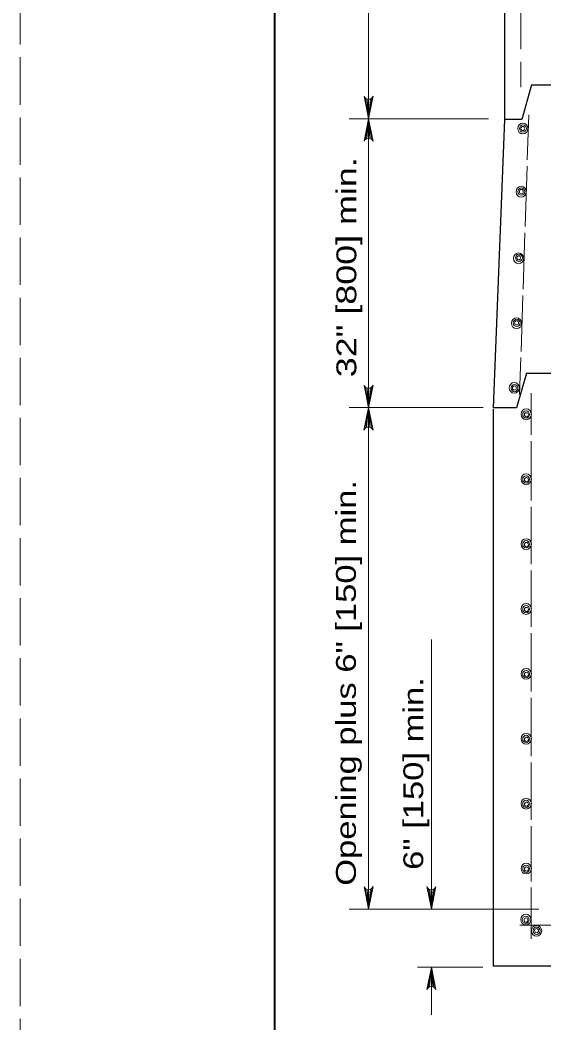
# Model space of a CAD drawing. Extents: x 808.4 to 842.4, y 1034.6 to 1056.6.
# Drawn here: x 808.44 to 812.55, y 1039.13 to 1047.01 of the extents above; entities that cross this region are included whole.
import ezdxf

# ---------------------------------------------------------------- set-up
doc = ezdxf.new("R2010")
doc.units = 0
doc.header["$LTSCALE"] = 0.062
doc.linetypes.add('LONG_DASHED', pattern=[7.5, 6, -1.5])
doc.layers.add('1', color=7, linetype='Continuous', lineweight=13)
doc.layers.add('10', color=7, linetype='Continuous')

msp = doc.modelspace()

# ---------------------------------------------------------------- linework, layer by layer
at = {"layer": '1', "linetype": 'LONG_DASHED'}
msp.add_line((812.37008, 1051.40067), (812.37008, 1046.4815), dxfattribs=at)
at = {"layer": '1'}
for p, q in [((811.17467, 1051.31167), (811.17467, 1046.23342)), ((811.15225, 1046.39358), (811.17467, 1046.23342)), ((811.16333, 1046.38817), (811.17467, 1046.23342)), ((811.19942, 1046.3955), (811.17467, 1046.23342)), ((811.18908, 1046.38933), (811.17467, 1046.23342)), ((811.17467, 1046.3865), (811.17467, 1046.23342)), ((811.022, 1046.23342), (812.11558, 1046.23342)), ((811.14983, 1046.07125), (811.17467, 1046.23342)), ((811.16025, 1046.07742), (811.17467, 1046.23342)), ((811.17467, 1046.23342), (811.17467, 1043.96608)), ((811.17467, 1046.08025), (811.17467, 1046.23342)), ((811.186, 1046.07858), (811.17467, 1046.23342)), ((811.19708, 1046.07317), (811.17467, 1046.23342)), ((812.43325, 1046.26425), (812.4215, 1045.91)), ((812.41983, 1045.86083), (812.40425, 1045.3855)), ((812.40267, 1045.33642), (812.38808, 1044.89383)), ((812.38642, 1044.84467), (812.372, 1044.40625)), ((812.3705, 1044.35717), (812.36092, 1044.06775)), ((811.15225, 1044.12375), (811.17467, 1043.9635)), ((811.16333, 1044.11825), (811.17467, 1043.9635)), ((811.19942, 1044.12558), (811.17467, 1043.9635)), ((811.18908, 1044.1195), (811.17467, 1043.9635)), ((811.17467, 1044.11667), (811.17467, 1043.9635)), ((812.45225, 1044.07833), (812.45225, 1043.75075)), ((811.022, 1043.96433), (812.07508, 1043.96433)), ((811.14967, 1043.80267), (811.17442, 1043.96475)), ((811.16, 1043.80875), (811.17442, 1043.96475)), ((811.17442, 1043.81158), (811.17442, 1043.96475)), ((811.18575, 1043.80992), (811.17442, 1043.96475)), ((811.19683, 1043.8045), (811.17442, 1043.96475)), ((811.17467, 1043.95367), (811.17467, 1040.02467)), ((812.45225, 1043.70158), (812.45225, 1043.23442)), ((812.45225, 1043.18533), (812.45225, 1042.73458)), ((812.45225, 1042.68542), (812.45225, 1042.24283)), ((811.66783, 1042.14333), (811.66783, 1040.02467)), ((812.45225, 1042.19367), (812.45225, 1041.73483)), ((812.45225, 1041.68567), (812.45225, 1041.22675)), ((812.45225, 1041.17758), (812.45225, 1040.72692)), ((812.45225, 1040.67775), (812.45225, 1040.24342)), ((811.15225, 1040.18492), (811.17467, 1040.02467)), ((811.16333, 1040.1795), (811.17467, 1040.02467)), ((811.19942, 1040.18683), (811.17467, 1040.02467)), ((811.18908, 1040.18067), (811.17467, 1040.02467)), ((811.17467, 1040.17783), (811.17467, 1040.02467)), ((811.64542, 1040.18492), (811.66783, 1040.02467)), ((811.6565, 1040.1795), (811.66783, 1040.02467)), ((811.69258, 1040.18683), (811.66783, 1040.02467)), ((811.68225, 1040.18067), (811.66783, 1040.02467)), ((811.66783, 1040.17783), (811.66783, 1040.02467)), ((812.45225, 1040.19425), (812.45225, 1039.79125)), ((812.51283, 1040.02467), (811.022, 1040.02467)), ((812.67817, 1039.89975), (812.36392, 1039.89975)), ((812.07308, 1039.56975), (811.56033, 1039.56975)), ((811.643, 1039.40758), (811.66783, 1039.56975)), ((811.65342, 1039.41375), (811.66783, 1039.56975)), ((811.66783, 1039.56975), (811.66783, 1039.19467)), ((811.66783, 1039.41658), (811.66783, 1039.56975)), ((811.67917, 1039.41492), (811.66783, 1039.56975)), ((811.69025, 1039.4095), (811.66783, 1039.56975))]:
    msp.add_line(p, q, dxfattribs=at)
at = {"layer": '1', "lineweight": 25}
for p, q in [((812.24142, 1051.31108), (812.24142, 1046.22592)), ((812.45517, 1046.49917), (816.43017, 1046.49917)), ((812.24142, 1046.22592), (812.15292, 1043.96275)), ((812.37825, 1046.22592), (812.24208, 1046.22592)), ((812.15217, 1043.95175), (812.15217, 1039.57592)), ((812.33733, 1043.96275), (812.15825, 1043.96275)), ((817.311, 1039.57592), (812.15217, 1039.57592))]:
    msp.add_line(p, q, dxfattribs=at)
at = {"layer": '1', "linetype": 'LONG_DASHED'}
msp.add_lwpolyline([(808.43883, 1034.62767), (842.43883, 1034.62767), (842.43883, 1056.62767), (808.43883, 1056.62767)], close=True, dxfattribs=at)
at = {"layer": '1', "lineweight": 25}
msp.add_lwpolyline([(810.43883, 1056.12767), (841.93883, 1056.12767), (841.93883, 1035.12767), (810.43883, 1035.12767)], close=True, dxfattribs=at)
at = {"layer": '1', "lineweight": 40}
msp.add_lwpolyline([(810.43883, 1056.12767), (841.93883, 1056.12767), (841.93883, 1035.12767), (810.43883, 1035.12767)], close=True, dxfattribs=at)
at = {"layer": '1', "lineweight": 25}
for points in [[(812.45517, 1046.49917), (812.37758, 1046.22592), (812.24408, 1046.22592)], [(812.41425, 1044.23608), (812.33658, 1043.96275), (812.15292, 1043.96275)], [(812.41425, 1044.23608), (817.05442, 1044.23608), (817.13217, 1043.96275), (817.31108, 1043.96275)]]:
    msp.add_lwpolyline(points, dxfattribs=at)
at = {"layer": '1'}
for points in [[(811.21008, 1046.41042), (811.17467, 1046.23342), (811.13925, 1046.41042)], [(811.13925, 1046.05642), (811.17467, 1046.23342), (811.21008, 1046.05642)], [(811.21008, 1044.1405), (811.17467, 1043.9635), (811.13925, 1044.1405)], [(811.139, 1043.78775), (811.17442, 1043.96475), (811.20983, 1043.78775)], [(811.21008, 1040.20167), (811.17467, 1040.02467), (811.13925, 1040.20167)], [(811.70325, 1040.20167), (811.66783, 1040.02467), (811.63242, 1040.20167)], [(811.63242, 1039.39275), (811.66783, 1039.56975), (811.70325, 1039.39275)]]:
    msp.add_lwpolyline(points, dxfattribs=at)
for centre, start, end in [((811.17461, 1046.42467), 202.08782, 337.91395), ((811.17469, 1046.04208), 22.08782, 157.91395), ((811.17461, 1044.15476), 202.08782, 337.91395), ((811.17446, 1043.77348), 22.08782, 157.91395), ((811.17461, 1040.216), 202.08782, 337.91395), ((811.66777, 1040.216), 202.08782, 337.91395), ((811.66785, 1039.37842), 22.08782, 157.91395)]:
    msp.add_arc(centre, 0.0382, start, end, dxfattribs=at)
for centre, major_axis in [((812.38635, 1046.15631), (0, 0.04232)), ((812.38667, 1046.15626), (0, -0.02865)), ((812.38604, 1046.15659), (0, -0.01649)), ((812.3729, 1045.65963), (0, 0.04232)), ((812.3751, 1045.66063), (0, -0.02865)), ((812.37448, 1045.66096), (0, -0.01649)), ((812.35315, 1045.13696), (0, 0.04232)), ((812.35528, 1045.14043), (0, -0.02865)), ((812.35465, 1045.14076), (0, -0.01649)), ((812.33664, 1044.62728), (0, 0.04232)), ((812.33829, 1044.62939), (0, -0.02865)), ((812.33766, 1044.62972), (0, -0.01649)), ((812.31933, 1044.11977), (0, 0.04232)), ((812.3209, 1044.11793), (0, -0.02865)), ((812.32027, 1044.11826), (0, -0.01649)), ((812.41302, 1043.91197), (0, 0.04232)), ((812.41231, 1043.9103), (0, -0.02865)), ((812.41428, 1043.90789), (0, -0.01649)), ((812.41302, 1043.40226), (0, 0.04232)), ((812.41231, 1043.40059), (0, -0.02865)), ((812.41428, 1043.39818), (0, -0.01649)), ((812.41302, 1042.89255), (0, 0.04232)), ((812.41231, 1042.89089), (0, -0.02865)), ((812.41428, 1042.88847), (0, -0.01649)), ((812.41302, 1042.38285), (0, 0.04232)), ((812.41231, 1042.38118), (0, -0.02865)), ((812.41428, 1042.37877), (0, -0.01649)), ((812.41302, 1041.87314), (0, 0.04232)), ((812.41231, 1041.87148), (0, -0.02865)), ((812.41428, 1041.86906), (0, -0.01649)), ((812.41302, 1041.36343), (0, 0.04232)), ((812.41231, 1041.36177), (0, -0.02865)), ((812.41428, 1041.35935), (0, -0.01649)), ((812.41302, 1040.85373), (0, 0.04232)), ((812.41231, 1040.85206), (0, -0.02865)), ((812.41428, 1040.84965), (0, -0.01649)), ((812.41302, 1040.34402), (0, 0.04232)), ((812.41231, 1040.34236), (0, -0.02865)), ((812.41428, 1040.33994), (0, -0.01649)), ((812.4098, 1039.94325), (0, 0.04232)), ((812.40909, 1039.94159), (0, -0.02865)), ((812.41106, 1039.93917), (0, -0.01649)), ((812.49413, 1039.85497), (0, 0.04232)), ((812.49413, 1039.8558), (0, -0.02865)), ((812.49421, 1039.85605), (0, -0.01649))]:
    msp.add_ellipse(centre, major_axis=major_axis, ratio=0.944544, dxfattribs=at)

# ---------------------------------------------------------------- texts
at = {"layer": '10'}
for s, width, p in [('32" [800] min.', 1.35, (811.07875, 1044.20283)), ('Opening plus 6" [150] min.', 1.3, (811.07542, 1040.20875)), ('6" [150] min.', 1.3, (811.60425, 1040.33367))]:
    msp.add_text(s, height=0.156, rotation=90, dxfattribs=dict(at, width=width)).set_placement(p)

doc.saveas('drawing.dxf')
